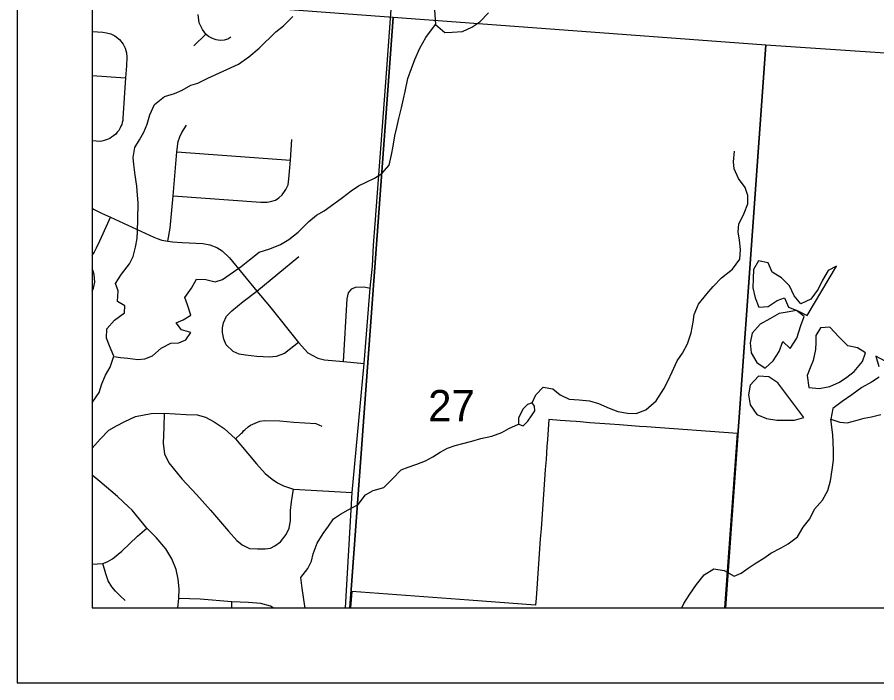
# Model space of a CAD drawing. Extents: x 0 to 34, y 0 to 22.
# Drawn here: x 2 to 3.147, y 14 to 14.889 of the extents above; entities that cross this region are included whole.
import ezdxf

# ---------------------------------------------------------------- set-up
doc = ezdxf.new("R2010")
doc.units = 0
for name, color, linetype in [('GM_X_City_Street', 7, 'Continuous'), ('GM_X_Corporation', 7, 'Continuous'), ('GM_X_County_Road', 7, 'Continuous'), ('GM_X_Minor_Lake', 7, 'Continuous'), ('GM_X_Minor_River', 7, 'Continuous'), ('GM_X_Section_Text', 7, 'Continuous'), ('GM_X_Township_Road', 7, 'Continuous'), ('GM_X_Unincorporated_Text', 7, 'Continuous'), ('SH_Cut_Line', 7, 'Continuous'), ('SH_Data', 7, 'Continuous')]:
    doc.layers.add(name, color=color, linetype=linetype)

msp = doc.modelspace()

# ---------------------------------------------------------------- linework, layer by layer
at = {"layer": 'GM_X_City_Street'}
msp.add_lwpolyline([(2.445, 14.1), (2.9445, 14.1), (2.9615, 14.3329), (2.8401, 14.3419), (2.8307, 14.3426), (2.8042, 14.3446), (2.791, 14.3456), (2.7778, 14.3466), (2.7645, 14.3475), (2.7513, 14.3485), (2.746, 14.3489), (2.7381, 14.3495), (2.7249, 14.3505), (2.7098, 14.3516), (2.7078, 14.3249), (2.7072, 14.3155), (2.7059, 14.2981), (2.705, 14.2849), (2.704, 14.2716), (2.7031, 14.2584), (2.7021, 14.2452), (2.7012, 14.232), (2.7002, 14.2187), (2.6993, 14.2055), (2.6983, 14.1923), (2.6974, 14.1791), (2.6965, 14.1658), (2.6955, 14.1526), (2.6946, 14.1394), (2.6936, 14.1262), (2.6927, 14.113), (2.692, 14.1038), (2.6031, 14.1104), (2.4467, 14.122)], close=True, dxfattribs=at)
at = {"layer": 'GM_X_Corporation'}
msp.add_lwpolyline([(2.1, 15.9442), (2.1, 14.1), (4.9875, 14.1), (5.0611, 15.2147), (5.0952, 15.7318), (4.92, 15.7429), (4.5905, 15.7634), (4.2803, 15.787), (3.9945, 15.8088), (3.3132, 15.8609), (2.8362, 15.8952), (2.7799, 15.8989), (2.6921, 15.9056), (2.5827, 15.9132), (2.2903, 15.9292)], close=True, dxfattribs=at)
at = {"layer": 'GM_X_County_Road'}
msp.add_lwpolyline([(2.4382, 14.1), (2.4471, 14.2544), (2.463, 14.4267), (2.4714, 14.527), (2.4741, 14.5565), (2.4756, 14.5845), (2.478, 14.6131), (2.4934, 14.8203), (2.5053, 14.9857), (2.5078, 15.0263), (2.5135, 15.1067), (2.5177, 15.1629), (2.5216, 15.2123), (2.526, 15.2791), (2.5346, 15.4013)], dxfattribs=at)
at = {"layer": 'GM_X_Minor_Lake'}
for points in [[(2.5528, 14.9644), (2.5583, 14.8793)], [(2.5583, 14.8793), (2.5707, 14.8689), (2.5806, 14.8692), (2.5946, 14.8702), (2.6068, 14.8758), (2.6175, 14.8829), (2.6293, 14.8949)], [(3.0935, 14.5564), (3.0825, 14.5508), (3.0751, 14.538), (3.0693, 14.5259), (3.0593, 14.5127), (3.046, 14.5064), (3.037, 14.5168), (3.0311, 14.5305), (3.0203, 14.5412), (3.0078, 14.5486), (3.0023, 14.5612), (2.9894, 14.5639), (2.9829, 14.5523), (2.9824, 14.5401), (2.9822, 14.5276), (2.9851, 14.5143), (2.9899, 14.5017), (3.0024, 14.5027), (3.0146, 14.5105), (3.0241, 14.5142), (3.0297, 14.502), (3.0421, 14.497), (3.0546, 14.4908)], [(3.0546, 14.4908), (3.0935, 14.5564)], [(3.0461, 14.4772), (3.0504, 14.4893), (3.0402, 14.4974), (3.0277, 14.4949), (3.0171, 14.4934), (3.0049, 14.486), (2.9919, 14.4789), (2.9812, 14.4669), (2.9784, 14.454), (2.9798, 14.4407), (2.9872, 14.4277), (2.9985, 14.4204), (3.0092, 14.4301), (3.0173, 14.4426), (3.022, 14.4558), (3.0317, 14.4466), (3.0406, 14.4602)], [(3.0406, 14.4602), (3.0461, 14.4772)], [(3.0569, 14.3943), (3.0706, 14.3931), (3.085, 14.396), (3.0975, 14.4015), (3.1075, 14.4082), (3.1174, 14.4157), (3.1285, 14.4293), (3.1324, 14.441), (3.1215, 14.4476), (3.109, 14.45), (3.0967, 14.4623), (3.0847, 14.4753), (3.0722, 14.4743), (3.066, 14.4641), (3.0663, 14.4546), (3.0658, 14.4451), (3.0626, 14.4307), (3.0584, 14.4209), (3.0545, 14.4107)], [(3.1585, 14.4297), (3.1464, 14.4363), (3.15, 14.4226)], [(3.0153, 14.4005), (3.0033, 14.4086), (2.9897, 14.4095), (2.9786, 14.3974), (2.9761, 14.3846), (2.9783, 14.3713), (2.9872, 14.3586), (3.0004, 14.3532), (3.014, 14.3508), (3.0243, 14.3507), (3.0375, 14.3509), (3.0501, 14.3542)], [(3.0545, 14.4107), (3.0569, 14.3943)], [(3.1506, 14.4082), (3.1403, 14.4015), (3.1274, 14.3944), (3.114, 14.3846), (3.1014, 14.3757), (3.0888, 14.3663), (3.086, 14.3523)], [(3.0501, 14.3542), (3.0153, 14.4005)], [(2.6874, 14.3739), (2.6813, 14.3717), (2.6752, 14.3661), (2.669, 14.354), (2.6693, 14.3456), (2.6753, 14.3433), (2.6818, 14.3497), (2.6864, 14.3565), (2.691, 14.3632), (2.6907, 14.3697)], [(2.6907, 14.3697), (2.6874, 14.3739)], [(3.0981, 14.3484), (3.1079, 14.3471), (3.1212, 14.3508), (3.1307, 14.3534), (3.1402, 14.3551), (3.1528, 14.3584)], [(3.086, 14.3523), (3.0981, 14.3484)]]:
    msp.add_lwpolyline(points, dxfattribs=at)
at = {"layer": 'GM_X_Minor_River'}
for points in [[(2.2956, 14.8266), (2.3094, 14.8363), (2.3228, 14.8476), (2.3453, 14.8697), (2.3557, 14.8776), (2.3679, 14.89)], [(2.2988, 14.5563), (2.3099, 14.5649), (2.3228, 14.5751), (2.3373, 14.5798), (2.3517, 14.5854), (2.3624, 14.5921), (2.375, 14.6022), (2.3892, 14.6161), (2.3995, 14.6247), (2.4098, 14.6303), (2.4228, 14.6397), (2.4343, 14.6483), (2.4457, 14.6573), (2.4556, 14.664), (2.4659, 14.6688), (2.477, 14.674), (2.4869, 14.6804), (2.4965, 14.6913), (2.4996, 14.7053), (2.5017, 14.7167), (2.5041, 14.7307), (2.5069, 14.742), (2.5096, 14.7538), (2.5128, 14.7682), (2.5156, 14.7799), (2.518, 14.7901), (2.5216, 14.8072), (2.5263, 14.8204), (2.5306, 14.8325), (2.5375, 14.8476), (2.5453, 14.862), (2.5583, 14.8793)], [(2.16, 14.5933), (2.1605, 14.6039), (2.1611, 14.6183), (2.1615, 14.6411), (2.1608, 14.6514), (2.1595, 14.6635), (2.1574, 14.678), (2.1558, 14.6924), (2.1548, 14.7019), (2.1572, 14.7152), (2.1634, 14.7253), (2.1692, 14.7355), (2.1736, 14.7464), (2.1771, 14.7585), (2.1834, 14.7725), (2.1968, 14.7833), (2.2101, 14.7873), (2.22, 14.7917), (2.2318, 14.7984), (2.2413, 14.8009), (2.2547, 14.8076), (2.2956, 14.8266)], [(2.6874, 14.3739), (2.6923, 14.3849), (2.702, 14.395), (2.7152, 14.3926), (2.725, 14.3845), (2.737, 14.3787), (2.7503, 14.3778), (2.7639, 14.3765), (2.776, 14.373), (2.79, 14.3671), (2.802, 14.3625), (2.8145, 14.3601), (2.8262, 14.3599), (2.8392, 14.3647), (2.8529, 14.3767), (2.8633, 14.3929), (2.8684, 14.4028), (2.8742, 14.4152), (2.8812, 14.43), (2.8881, 14.4405), (2.8947, 14.4526), (2.8998, 14.4673), (2.9022, 14.4817), (2.9038, 14.492), (2.9096, 14.5056), (2.9208, 14.5195), (2.9292, 14.5293), (2.9403, 14.5409), (2.9548, 14.5525), (2.9645, 14.5657), (2.9654, 14.579), (2.964, 14.5912), (2.9622, 14.6026), (2.9631, 14.6128), (2.9704, 14.6275), (2.9755, 14.64), (2.9752, 14.651), (2.9716, 14.6617), (2.963, 14.6735), (2.957, 14.6865), (2.9564, 14.696), (2.9577, 14.71)], [(2.1, 14.374), (2.1005, 14.3747), (2.1094, 14.3879), (2.113, 14.3992), (2.1177, 14.4109), (2.1239, 14.4215), (2.129, 14.4362), (2.1232, 14.4503), (2.1191, 14.4606), (2.1197, 14.4728), (2.1297, 14.4844), (2.1431, 14.4941), (2.1436, 14.5036), (2.1338, 14.5094), (2.1348, 14.5234), (2.1312, 14.5333), (2.1393, 14.5461), (2.1501, 14.5596), (2.1548, 14.5695), (2.158, 14.5819), (2.16, 14.5933)], [(2.1289, 14.436), (2.1381, 14.4346), (2.1479, 14.4337), (2.1611, 14.432), (2.1706, 14.4326), (2.1805, 14.4366), (2.192, 14.4471), (2.205, 14.4538), (2.2156, 14.454), (2.2251, 14.458), (2.232, 14.4678), (2.2192, 14.4714), (2.2122, 14.481), (2.2217, 14.485), (2.232, 14.4913), (2.2273, 14.5047), (2.2236, 14.5146), (2.2329, 14.5274), (2.2395, 14.5391), (2.2516, 14.5389), (2.2644, 14.5357), (2.2739, 14.5386), (2.2988, 14.5563)], [(2.3844, 14.1), (2.384, 14.1023), (2.3805, 14.1266), (2.3788, 14.1407), (2.388, 14.1527), (2.3927, 14.1625), (2.395, 14.1724), (2.4005, 14.1864), (2.4086, 14.1996), (2.4155, 14.2094), (2.4221, 14.2192), (2.4316, 14.2255), (2.4419, 14.2311), (2.4552, 14.2382), (2.4648, 14.251), (2.4751, 14.2569), (2.4896, 14.261), (2.5007, 14.2722), (2.5125, 14.2846), (2.522, 14.288), (2.5334, 14.292), (2.5449, 14.2964), (2.5548, 14.3017), (2.5647, 14.308), (2.5746, 14.3136), (2.5845, 14.3169), (2.5951, 14.3198), (2.6069, 14.3227), (2.6191, 14.3264), (2.6335, 14.3297), (2.6468, 14.3345), (2.6563, 14.3397), (2.6693, 14.3456)], [(2.8872, 14.1), (2.8898, 14.1061), (2.8979, 14.1182), (2.9067, 14.1314), (2.9171, 14.1442), (2.9301, 14.1524), (2.9437, 14.15), (2.9569, 14.1426), (2.9664, 14.1463), (2.9759, 14.153), (2.9866, 14.1601), (2.9965, 14.1665), (3.0061, 14.1732), (3.0198, 14.1803), (3.0293, 14.1855), (3.0415, 14.1949), (3.0492, 14.2077), (3.0581, 14.219), (3.0643, 14.2318), (3.075, 14.2439), (3.082, 14.2571), (3.0855, 14.2696), (3.0879, 14.2847), (3.0896, 14.2976), (3.0897, 14.3098), (3.0891, 14.3219), (3.0888, 14.3314), (3.086, 14.3523)]]:
    msp.add_lwpolyline(points, dxfattribs=at)
at = {"layer": 'GM_X_Township_Road'}
for p, q in [((2.2359, 14.851), (2.2518, 14.8665)), ((2.1, 14.8112), (2.1447, 14.808)), ((2.213, 14.7091), (2.3647, 14.6981)), ((2.3198, 14.5231), (2.3761, 14.5697)), ((2.2863, 14.1), (2.2867, 14.1082))]:
    msp.add_line(p, q, dxfattribs=at)
for points in [[(2.285, 14.8623), (2.281, 14.8598), (2.2765, 14.8586), (2.2709, 14.8581), (2.2658, 14.8591), (2.2608, 14.8609), (2.2554, 14.8635), (2.2518, 14.8665), (2.2472, 14.8728), (2.243, 14.8814), (2.2415, 14.8928)], [(2.1, 14.87), (2.1144, 14.869), (2.1192, 14.8683), (2.125, 14.8669), (2.1305, 14.8642), (2.1366, 14.8594), (2.1414, 14.8532), (2.1442, 14.8477), (2.1457, 14.8417), (2.1463, 14.8358), (2.1459, 14.8242), (2.1447, 14.808), (2.1412, 14.7542), (2.1408, 14.7511), (2.1402, 14.7485), (2.1395, 14.746), (2.1385, 14.7435), (2.1376, 14.7414), (2.1365, 14.7395), (2.1355, 14.7378), (2.1336, 14.7354), (2.1315, 14.7331), (2.1287, 14.7306), (2.1261, 14.7287), (2.1238, 14.7273), (2.1215, 14.7261), (2.1188, 14.7251), (2.1161, 14.7243), (2.113, 14.7237), (2.1095, 14.7233), (2.1056, 14.7234), (2.1, 14.7238)], [(2.2012, 14.5899), (2.2041, 14.6074), (2.2082, 14.6507), (2.213, 14.7091), (2.2151, 14.7231), (2.2169, 14.7295), (2.2197, 14.7352), (2.2258, 14.7448)], [(2.2082, 14.6507), (2.3252, 14.6421), (2.3337, 14.6419), (2.3382, 14.6428), (2.345, 14.6449), (2.3494, 14.648), (2.3538, 14.652), (2.3587, 14.6589), (2.3615, 14.6652), (2.3627, 14.6732), (2.3635, 14.6831), (2.3647, 14.6981), (2.3668, 14.7256)], [(2.1, 14.6342), (2.1018, 14.6328), (2.1124, 14.6274), (2.1244, 14.6219), (2.1823, 14.5953), (2.1868, 14.5936), (2.1929, 14.5914), (2.2012, 14.5899), (2.2074, 14.5889), (2.22, 14.5883), (2.2476, 14.587), (2.2573, 14.5852), (2.2663, 14.5816), (2.2736, 14.5771), (2.2835, 14.5677), (2.3198, 14.5231), (2.3368, 14.503), (2.3754, 14.4545), (2.3881, 14.4408), (2.4013, 14.4338), (2.4102, 14.4313), (2.4355, 14.429), (2.463, 14.4267)], [(2.1, 14.571), (2.1029, 14.5747), (2.106, 14.5812), (2.1102, 14.5906), (2.1211, 14.6142), (2.1244, 14.6219)], [(2.1, 14.5233), (2.1017, 14.5271), (2.1036, 14.5351), (2.1026, 14.5454), (2.1008, 14.5513), (2.1, 14.5526)], [(2.4355, 14.429), (2.4405, 14.513), (2.4422, 14.521), (2.4465, 14.5262), (2.4516, 14.5286), (2.4633, 14.529), (2.4714, 14.527)], [(2.3754, 14.4545), (2.3569, 14.4397), (2.3455, 14.4357), (2.337, 14.4349), (2.3198, 14.4361), (2.3046, 14.4378), (2.2963, 14.4389), (2.2884, 14.4427), (2.279, 14.4513), (2.2758, 14.459), (2.2739, 14.4679), (2.2739, 14.474), (2.2756, 14.481), (2.2795, 14.4898), (2.2863, 14.4971), (2.3017, 14.5092), (2.3198, 14.5231)], [(2.1, 14.3133), (2.1106, 14.3256), (2.1224, 14.3374), (2.1325, 14.3435), (2.1439, 14.3492), (2.1578, 14.3557), (2.1789, 14.3598), (2.1963, 14.3603), (2.2257, 14.3586), (2.2403, 14.3578), (2.2513, 14.3549), (2.2631, 14.3488), (2.2765, 14.3395), (2.2915, 14.326), (2.3078, 14.3065), (2.3196, 14.2923), (2.331, 14.2797), (2.3403, 14.2719), (2.3473, 14.2671), (2.3554, 14.263), (2.3688, 14.2585), (2.4471, 14.2544)], [(2.1963, 14.3603), (2.1956, 14.3415), (2.1948, 14.3195), (2.1968, 14.3057), (2.2025, 14.2939), (2.2196, 14.2727), (2.2395, 14.2516), (2.2582, 14.2308), (2.2822, 14.2024), (2.2932, 14.1902), (2.3001, 14.1845), (2.3102, 14.1796), (2.3208, 14.1788), (2.331, 14.1788), (2.3383, 14.18), (2.344, 14.1828), (2.3513, 14.1885), (2.3591, 14.1983), (2.3631, 14.2064), (2.3647, 14.2162), (2.3647, 14.23), (2.366, 14.2418), (2.3688, 14.2585)], [(2.2915, 14.326), (2.2979, 14.3323), (2.2994, 14.3334), (2.3007, 14.3345), (2.3023, 14.3368), (2.3039, 14.3379), (2.3084, 14.3418), (2.3115, 14.3443), (2.3237, 14.3496), (2.3306, 14.3505), (2.3504, 14.35), (2.3693, 14.3481), (2.3985, 14.3464), (2.4066, 14.3429)], [(2.1485, 14.2352), (2.1341, 14.2487), (2.1105, 14.269), (2.1, 14.2776)], [(2.2146, 14.1), (2.2157, 14.1125), (2.216, 14.1254), (2.2147, 14.1385), (2.212, 14.1512), (2.2064, 14.1656), (2.1983, 14.1789), (2.1856, 14.1942), (2.1732, 14.2067), (2.1533, 14.2307), (2.1485, 14.2352)], [(2.1, 14.1585), (2.1142, 14.1593), (2.118, 14.1608), (2.1212, 14.1621), (2.1272, 14.1655), (2.1396, 14.1757), (2.1607, 14.1959), (2.1732, 14.2067)], [(2.144, 14.1098), (2.1375, 14.116), (2.1311, 14.1224), (2.1263, 14.1281), (2.1215, 14.1362), (2.1183, 14.1456), (2.1142, 14.1593)], [(2.3415, 14.1), (2.3381, 14.1024), (2.3254, 14.1058), (2.3086, 14.1072), (2.2867, 14.1082), (2.2443, 14.1117), (2.2157, 14.1125)]]:
    msp.add_lwpolyline(points, dxfattribs=at)
at = {"layer": 'GM_X_Unincorporated_Text'}
for points in [[(2.1, 14.9192), (2.1, 14.1), (2.4441, 14.1), (2.5017, 14.8889)], [(2.4441, 14.1), (2.9453, 14.1), (2.9993, 14.8517), (2.5017, 14.8889)], [(2.9453, 14.1), (3.4598, 14.1), (3.51, 14.8176), (2.9993, 14.8517)]]:
    msp.add_lwpolyline(points, close=True, dxfattribs=at)
at = {"layer": 'SH_Cut_Line'}
msp.add_lwpolyline([(2.1, 15.9442), (2.1, 14.1), (8.9, 14.1), (8.9, 15.4827), (8.6741, 15.4976), (7.6503, 15.5653), (6.838, 15.6206), (6.624, 15.6351), (6.4, 15.6498), (6.1109, 15.6683), (5.9419, 15.6782), (5.0952, 15.7318), (4.92, 15.7429), (4.5905, 15.7634), (4.2803, 15.787), (3.9945, 15.8088), (3.3132, 15.8609), (2.8362, 15.8952), (2.7799, 15.8989), (2.6921, 15.9056), (2.5827, 15.9132), (2.2903, 15.9292)], close=True, dxfattribs=at)
at = {"layer": 'SH_Data'}
for p, q in [((2, 21), (2, 14)), ((2, 14), (9, 14))]:
    msp.add_line(p, q, dxfattribs=at)

# ---------------------------------------------------------------- texts
at = {"layer": 'GM_X_Section_Text'}
msp.add_text('27', height=0.04186, rotation=0, dxfattribs=at).set_placement((2.5486, 14.3493))

doc.saveas('drawing.dxf')
